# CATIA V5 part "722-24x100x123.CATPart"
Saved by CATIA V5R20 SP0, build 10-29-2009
Part number: 722-24x100x123
Definition: NONE
Nomenclature: 722-24x100x123
Source: Unknown
Description: 722-24x100x123
Bounding box of the stored display mesh (mm): x -12 to 12, y -11.818 to 11.818, z -88 to 35
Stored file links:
  C:\Users\Utente\Desktop\IO LAVORO\3D X SITO CF\X SITO\722\722-24x100x123.CATPart
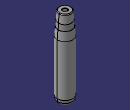
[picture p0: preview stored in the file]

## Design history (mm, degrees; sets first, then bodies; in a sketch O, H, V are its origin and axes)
Body1 "722-24x100x123" (main body)
  Solid1: solid without history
